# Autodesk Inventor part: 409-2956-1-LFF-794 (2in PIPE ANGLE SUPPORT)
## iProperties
Created: 2010-11
Part Number: 409-2956-1-LFF-794 (2in PIPE ANGLE SUPPORT)
Cost Center: 0 lbmass
Material: A304 STAINLESS STEEL
Document SubType Name: Sheet Metal
Designer: S. Boerckel
Authority: 0 in^3
Mass: 794.445 g
Surface Area: 357.51 cm^2
Volume: 98.3224 cm^3
Density: 8.08 g/cm^3
Flat Pattern Width: 5.08 cm
Flat Pattern Length: 35.56 cm
Flat Pattern Area: 180.645 cm^2
Sheet Metal Rule: 1/4"Thk
Author: S. Boerckel
Revision Number: 0
SaveDate: 2008-01-15
SaveTime: 10:24
FileName: Sheet Metal
Wide: =<Flat Pattern Width>cm
Length: =<Flat Pattern Length>cm
Thickness: 0.2500 in
SMR: =<Sheet Metal Rule> - <Material>
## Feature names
1. Plate1
